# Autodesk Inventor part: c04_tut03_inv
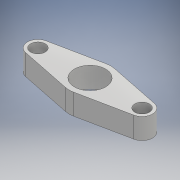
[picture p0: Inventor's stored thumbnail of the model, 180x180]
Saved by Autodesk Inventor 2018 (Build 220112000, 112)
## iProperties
Created: 2017-04
Part Number: c04_tut03_inv
Material: Generic
Document SubType Name: Modeling
Designer: CADCIM 00
Density: 1 g/cm^3
Appearance: Default
Author: CADCIM 00
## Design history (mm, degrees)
sketch "Sketch1"
  geometry: L1 (26, 4.899)-(2, 9.798); L2 (26, -4.899)-(2, -9.798); L3 (-2, 9.798)-(-26, 4.899); L4 (-2, -9.798)-(-26, -4.899); C1 r 3.5 at (25, 0); C2 r 3.5 at (-25, 0); C3 r 7.5 at (0, 0); A1 r 5 centre (-25, 0) between (-26, 4.899) and (-26, -4.899); A2 r 5 centre (25, 0) between (26, -4.899) and (26, 4.899); A3 r 10 centre (0, 0) between (-2, -9.798) and (2, -9.798); A4 r 10 centre (0, 0) between (2, 9.798) and (-2, 9.798); 1 further point
  constraints: 8 end point, 8 point on circle, 8 tangent, 7 centre point, 4 coincident, 2 equal length, 2 equal radius, 2 horizontal alignment
  dimensions: "d0" = 15 diameter of C3; "d1" = 10 radius of A4; "d2" = 50 distance of A1.centre A2.centre; "d3" = 7 diameter of C1; "d4" = 5 radius of A2
extrude "Extrusion1" new body sketch "Sketch1" distance "d5" = 10; taper "d6" = 0 deg
body "Solid1"
